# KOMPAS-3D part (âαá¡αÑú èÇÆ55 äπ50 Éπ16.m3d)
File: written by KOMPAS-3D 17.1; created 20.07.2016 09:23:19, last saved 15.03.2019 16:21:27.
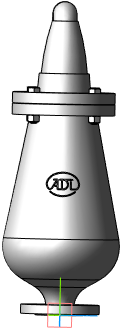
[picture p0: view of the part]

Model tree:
1. Операция без истории:2  (labels: Сталь 20  ГОСТ 1050-88)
